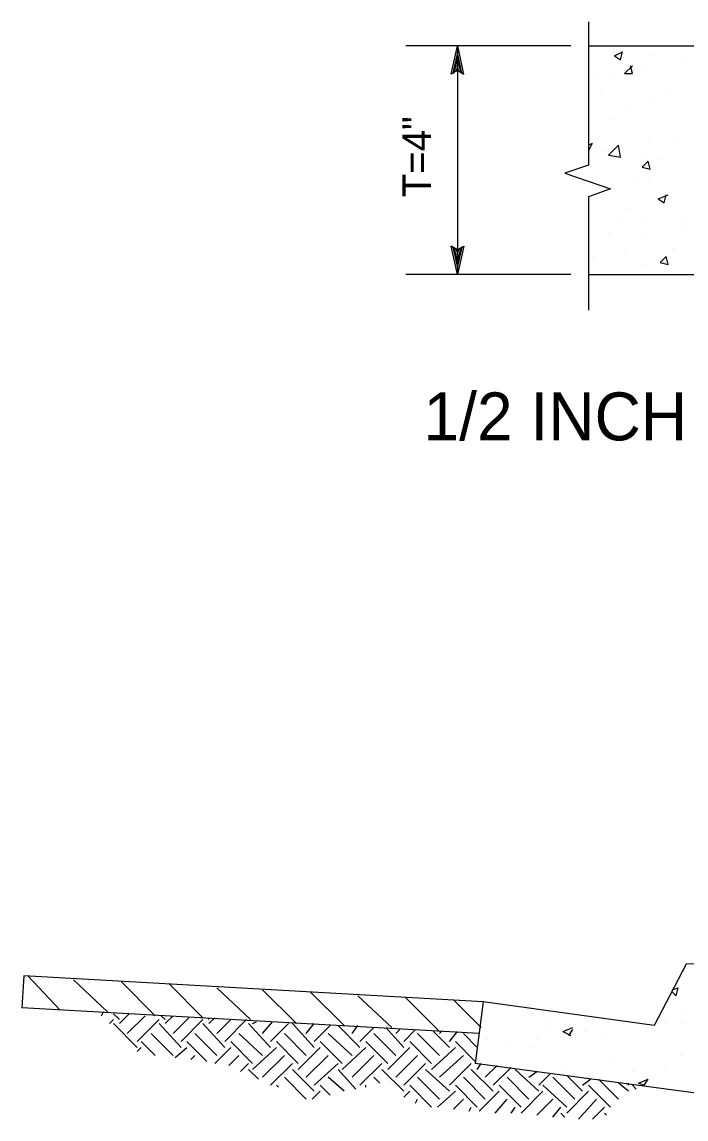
# Model space of a CAD drawing. Extents: x -118779 to -116979, y -104389 to -102939.
# Drawn here: x -118447.5 to -118309, y -103633.1 to -103404.1 of the extents above; entities that cross this region are included whole.
import ezdxf

# ---------------------------------------------------------------- set-up
doc = ezdxf.new("R2010")
doc.units = 0
for name, color, linetype in [('G-MARK', 7, 'Continuous'), ('G-TEXT', 7, 'Continuous'), ('Misc CnstDet(22)', 7, 'Continuous')]:
    doc.layers.add(name, color=color, linetype=linetype)

msp = doc.modelspace()

# ---------------------------------------------------------------- linework, layer by layer
at = {"layer": 'G-MARK'}
for p, q in [((-118333.05, -103409.09), (-118367.48, -103409.09)), ((-118356.7, -103409.09), (-118356.7, -103456.79)), ((-118333.05, -103456.79), (-118367.48, -103456.79))]:
    msp.add_line(p, q, dxfattribs=at)
at = {"layer": 'G-TEXT'}
for points in [[(-118358.01, -103415), (-118356.7, -103409.09), (-118355.39, -103415), (-118355.74, -103414.79), (-118356.69, -103410.46), (-118357.67, -103414.79), (-118357.32, -103414.58), (-118356.7, -103411.81), (-118356.08, -103414.58), (-118356.43, -103414.37), (-118356.7, -103413.17), (-118356.97, -103414.37), (-118356.7, -103414.21), (-118355.39, -103415), (-118356.7, -103414.21)], [(-118355.38, -103450.88), (-118356.7, -103456.79), (-118358.01, -103450.88), (-118357.66, -103451.09), (-118356.7, -103455.42), (-118355.73, -103451.09), (-118356.08, -103451.3), (-118356.69, -103454.07), (-118357.31, -103451.3), (-118356.96, -103451.51), (-118356.69, -103452.71), (-118356.42, -103451.51), (-118356.7, -103451.67), (-118358.01, -103450.88), (-118356.7, -103451.67)]]:
    msp.add_lwpolyline(points, close=True, dxfattribs=at)
at = {"layer": 'Misc CnstDet(22)'}
for p, q in [((-118329.32, -103409.09), (-118254.66, -103409.09)), ((-118329.32, -103409.09), (-118329.32, -103409.09)), ((-118323.93, -103411.16), (-118322.27, -103410.33)), ((-118323.93, -103411.16), (-118322.69, -103411.99)), ((-118322.69, -103411.99), (-118322.27, -103410.33)), ((-118316.05, -103411.16), (-118316.05, -103411.16)), ((-118321.86, -103414.9), (-118320.2, -103413.24)), ((-118320.2, -103414.9), (-118320.61, -103413.24)), ((-118317.29, -103414.07), (-118317.29, -103414.07)), ((-118309.41, -103412.41), (-118309.41, -103412.41)), ((-118327.25, -103415.31), (-118327.25, -103415.31)), ((-118324.76, -103415.31), (-118324.76, -103415.31)), ((-118321.86, -103414.9), (-118320.2, -103414.9)), ((-118326.83, -103418.22), (-118326.83, -103418.22)), ((-118316.46, -103419.87), (-118316.46, -103419.87)), ((-118312.73, -103419.04), (-118312.73, -103419.04)), ((-118321.03, -103421.95), (-118321.03, -103421.95)), ((-118324.34, -103424.44), (-118324.34, -103424.44)), ((-118329.32, -103431.07), (-118328.49, -103429.41)), ((-118329.32, -103429.83), (-118328.49, -103429.41)), ((-118325.17, -103431.9), (-118323.1, -103429.83)), ((-118322.69, -103432.32), (-118323.1, -103429.83)), ((-118316.88, -103428.58), (-118316.88, -103428.58)), ((-118310.66, -103428.17), (-118310.66, -103428.17)), ((-118329.32, -103431.07), (-118329.32, -103431.07)), ((-118326, -103431.07), (-118326, -103431.07)), ((-118325.17, -103431.9), (-118322.69, -103432.32)), ((-118317.71, -103432.32), (-118317.71, -103432.32)), ((-118330.98, -103434.81), (-118330.98, -103434.81)), ((-118318.12, -103434.39), (-118316.88, -103433.15)), ((-118318.12, -103434.39), (-118316.46, -103434.81)), ((-118316.46, -103434.81), (-118316.88, -103433.15)), ((-118314.39, -103432.73), (-118314.39, -103432.73)), ((-118319.78, -103436.88), (-118319.78, -103436.88)), ((-118316.88, -103437.29), (-118316.88, -103437.29)), ((-118314.8, -103441.03), (-118312.73, -103440.2)), ((-118314.8, -103441.03), (-118313.56, -103441.86)), ((-118313.56, -103441.86), (-118313.15, -103440.2)), ((-118321.44, -103443.1), (-118321.44, -103443.1)), ((-118314.8, -103442.27), (-118314.8, -103442.27)), ((-118323.1, -103445.59), (-118323.1, -103445.59)), ((-118317.29, -103446), (-118317.29, -103446)), ((-118309.83, -103446), (-118309.83, -103446)), ((-118325.17, -103448.49), (-118325.17, -103448.49)), ((-118309, -103446.42), (-118309, -103446.42)), ((-118317.29, -103449.32), (-118317.29, -103449.32)), ((-118321.86, -103452.64), (-118321.86, -103452.64)), ((-118314.39, -103454.3), (-118313.15, -103453.06)), ((-118312.73, -103454.71), (-118313.15, -103453.06)), ((-118311.9, -103451.4), (-118311.9, -103451.4)), ((-118328.49, -103453.47), (-118328.49, -103453.47)), ((-118317.71, -103454.71), (-118317.71, -103454.71)), ((-118314.39, -103454.3), (-118312.73, -103454.71)), ((-118356.7, -103456.79), (-118356.7, -103456.79)), ((-118329.32, -103456.79), (-118181.25, -103456.79)), ((-118329.32, -103456.79), (-118329.32, -103456.79)), ((-118100.79, -103593.66), (-118309, -103600.71)), ((-118309, -103600.71), (-118315.63, -103613.57)), ((-118309.83, -103601.96), (-118309.83, -103601.96)), ((-118447.11, -103603.2), (-118447.53, -103609.84)), ((-118351.3, -103608.59), (-118447.11, -103603.2)), ((-118439.65, -103610.25), (-118446.28, -103603.2)), ((-118429.69, -103610.67), (-118436.75, -103604.03)), ((-118419.74, -103611.5), (-118426.79, -103604.44)), ((-118409.79, -103611.91), (-118416.84, -103604.86)), ((-118399.83, -103612.32), (-118406.88, -103605.69)), ((-118390.29, -103613.15), (-118397.34, -103606.1)), ((-118380.34, -103613.57), (-118387.39, -103606.52)), ((-118311.9, -103606.1), (-118310.66, -103605.69)), ((-118311.9, -103606.52), (-118311.07, -103607.35)), ((-118311.07, -103607.35), (-118310.66, -103605.69)), ((-118370.38, -103613.98), (-118377.43, -103607.35)), ((-118360.43, -103614.81), (-118367.48, -103607.76)), ((-118351.72, -103613.98), (-118357.53, -103608.18)), ((-118351.3, -103608.59), (-118352.96, -103621.45)), ((-118315.63, -103613.57), (-118351.3, -103608.59)), ((-118350.89, -103608.59), (-118350.89, -103608.59)), ((-118352.13, -103615.23), (-118447.53, -103609.84)), ((-118430.94, -103611.5), (-118430.52, -103610.67)), ((-118427.21, -103612.32), (-118428.45, -103611.08)), ((-118427.21, -103613.15), (-118425.13, -103611.08)), ((-118309.83, -103611.08), (-118309.83, -103611.08)), ((-118429.28, -103613.15), (-118428.45, -103612.32)), ((-118423.47, -103618.13), (-118428.45, -103613.15)), ((-118425.55, -103615.23), (-118421.81, -103611.5)), ((-118423.47, -103616.89), (-118418.91, -103612.32)), ((-118414.35, -103618.13), (-118418.91, -103613.15)), ((-118417.67, -103612.32), (-118418.5, -103611.5)), ((-118417.67, -103613.15), (-118416.01, -103611.5)), ((-118416.01, -103615.23), (-118412.69, -103611.91)), ((-118414.35, -103616.89), (-118409.79, -103612.32)), ((-118405.22, -103618.13), (-118409.79, -103613.15)), ((-118408.54, -103612.32), (-118408.54, -103611.91)), ((-118408.54, -103613.15), (-118407.3, -103611.91)), ((-118406.88, -103615.23), (-118403.98, -103612.32)), ((-118405.22, -103616.89), (-118400.66, -103612.32)), ((-118395.68, -103618.13), (-118400.25, -103613.15)), ((-118399.42, -103613.15), (-118398.59, -103612.74)), ((-118397.34, -103615.23), (-118395.27, -103612.74)), ((-118395.68, -103616.89), (-118391.95, -103613.15)), ((-118386.56, -103618.13), (-118391.12, -103613.15)), ((-118389.88, -103613.15), (-118389.88, -103613.15)), ((-118388.22, -103615.23), (-118386.56, -103613.15)), ((-118351.72, -103611.5), (-118351.72, -103611.5)), ((-118337.62, -103611.91), (-118337.62, -103611.91)), ((-118323.51, -103612.74), (-118323.51, -103612.74)), ((-118323.51, -103612.74), (-118323.51, -103612.74)), ((-118313.56, -103612.74), (-118313.56, -103612.74)), ((-118310.24, -103612.74), (-118310.24, -103612.74)), ((-118309.41, -103613.15), (-118309.41, -103613.15)), ((-118416.01, -103619.79), (-118420.57, -103615.23)), ((-118406.88, -103619.79), (-118411.44, -103615.23)), ((-118397.34, -103619.79), (-118402.32, -103615.23)), ((-118388.22, -103619.79), (-118392.78, -103615.23)), ((-118386.56, -103616.89), (-118383.24, -103613.57)), ((-118378.68, -103619.79), (-118383.66, -103615.23)), ((-118377.02, -103618.13), (-118381.58, -103613.57)), ((-118378.68, -103615.23), (-118377.43, -103613.57)), ((-118377.02, -103616.89), (-118374.12, -103613.98)), ((-118369.55, -103619.79), (-118374.12, -103615.23)), ((-118367.89, -103618.13), (-118371.63, -103613.98)), ((-118369.55, -103615.23), (-118368.72, -103614.4)), ((-118367.89, -103616.89), (-118365.41, -103614.4)), ((-118360.43, -103619.79), (-118364.99, -103615.23)), ((-118358.36, -103618.13), (-118361.67, -103614.81)), ((-118360.43, -103615.23), (-118360.01, -103614.81)), ((-118358.36, -103616.89), (-118356.7, -103614.81)), ((-118352.55, -103618.13), (-118355.45, -103615.23)), ((-118337.2, -103614.81), (-118337.2, -103614.81)), ((-118334.71, -103614.81), (-118332.64, -103613.98)), ((-118334.71, -103614.81), (-118333.05, -103615.64)), ((-118333.47, -103615.64), (-118332.64, -103614.4)), ((-118330.15, -103614.81), (-118330.15, -103614.81)), ((-118325.59, -103615.23), (-118325.59, -103615.23)), ((-118419.74, -103619.79), (-118422.64, -103616.89)), ((-118408.96, -103621.03), (-118413.1, -103616.89)), ((-118399.42, -103621.45), (-118403.98, -103616.89)), ((-118389.88, -103621.45), (-118394.44, -103616.89)), ((-118380.75, -103621.45), (-118385.31, -103616.89)), ((-118371.21, -103621.45), (-118375.78, -103616.89)), ((-118362.09, -103621.45), (-118366.65, -103616.89)), ((-118352.96, -103621.03), (-118357.11, -103616.89)), ((-118350.47, -103616.47), (-118350.47, -103616.47)), ((-118346.74, -103616.89), (-118346.74, -103616.89)), ((-118340.11, -103616.06), (-118340.11, -103616.06)), ((-118423.47, -103618.96), (-118422.64, -103618.13)), ((-118415.59, -103620.21), (-118413.1, -103618.13)), ((-118412.27, -103620.62), (-118411.44, -103619.79)), ((-118407.3, -103621.45), (-118403.98, -103618.13)), ((-118404.39, -103621.86), (-118402.32, -103619.79)), ((-118399.42, -103622.69), (-118394.44, -103618.13)), ((-118397.34, -103624.35), (-118392.78, -103619.79)), ((-118389.88, -103622.69), (-118385.31, -103618.13)), ((-118388.22, -103624.35), (-118383.66, -103619.79)), ((-118380.75, -103622.69), (-118375.78, -103618.13)), ((-118378.68, -103624.35), (-118374.12, -103619.79)), ((-118371.21, -103622.69), (-118366.65, -103618.13)), ((-118369.55, -103624.35), (-118364.99, -103619.79)), ((-118362.09, -103622.69), (-118357.11, -103618.13)), ((-118360.43, -103624.35), (-118355.45, -103619.79)), ((-118340.93, -103618.13), (-118340.93, -103618.13)), ((-118310.24, -103619.79), (-118310.24, -103619.79)), ((-118401.91, -103623.11), (-118400.25, -103621.45)), ((-118395.68, -103626.01), (-118391.12, -103621.45)), ((-118386.56, -103626.01), (-118381.58, -103621.45)), ((-118377.02, -103626.01), (-118372.46, -103621.45)), ((-118367.89, -103626.01), (-118363.33, -103621.45)), ((-118358.36, -103626.01), (-118353.79, -103621.45)), ((-118297.8, -103628.92), (-118352.96, -103621.45)), ((-118352.55, -103621.45), (-118352.55, -103621.45)), ((-118352.55, -103622.69), (-118351.72, -103621.45)), ((-118350.89, -103624.35), (-118348.4, -103621.86)), ((-118349.23, -103626.01), (-118345.5, -103622.28)), ((-118348.4, -103621.86), (-118348.4, -103621.86)), ((-118323.93, -103621.45), (-118323.93, -103621.45)), ((-118313.56, -103622.28), (-118313.56, -103622.28)), ((-118398.17, -103624.77), (-118400.25, -103622.69)), ((-118388.22, -103628.92), (-118392.78, -103624.35)), ((-118386.56, -103627.26), (-118391.12, -103622.69)), ((-118380.34, -103627.26), (-118383.66, -103624.35)), ((-118377.85, -103626.84), (-118381.58, -103622.69)), ((-118372.87, -103625.6), (-118374.12, -103624.35)), ((-118367.89, -103627.26), (-118372.46, -103622.69)), ((-118360.43, -103628.92), (-118364.99, -103624.35)), ((-118358.36, -103627.26), (-118363.33, -103622.69)), ((-118350.89, -103628.92), (-118355.45, -103624.35)), ((-118349.23, -103627.26), (-118353.79, -103622.69)), ((-118341.76, -103628.92), (-118346.33, -103624.35)), ((-118339.69, -103627.26), (-118344.67, -103622.69)), ((-118341.76, -103624.35), (-118340.11, -103623.11)), ((-118339.69, -103626.01), (-118337.2, -103623.52)), ((-118332.22, -103628.92), (-118336.79, -103624.35)), ((-118334.3, -103622.69), (-118334.3, -103622.69)), ((-118330.57, -103627.26), (-118333.88, -103623.94)), ((-118332.22, -103624.35), (-118332.22, -103624.35)), ((-118330.57, -103626.01), (-118328.91, -103624.77)), ((-118323.1, -103628.92), (-118327.25, -103624.77)), ((-118320.2, -103623.11), (-118320.2, -103623.11)), ((-118320.2, -103623.11), (-118320.2, -103623.11)), ((-118318.95, -103625.6), (-118316.88, -103624.77)), ((-118317.71, -103626.01), (-118316.88, -103624.77)), ((-118394.02, -103626.43), (-118394.44, -103626.01)), ((-118383.24, -103628.09), (-118385.31, -103626.01)), ((-118375.78, -103626.43), (-118375.78, -103626.01)), ((-118362.09, -103630.57), (-118366.65, -103626.01)), ((-118352.55, -103630.57), (-118357.11, -103626.01)), ((-118343.42, -103630.57), (-118347.99, -103626.01)), ((-118333.88, -103630.57), (-118338.86, -103626.01)), ((-118324.76, -103630.57), (-118329.32, -103626.01)), ((-118321.03, -103627.26), (-118323.1, -103625.6)), ((-118321.03, -103626.01), (-118321.03, -103625.6)), ((-118319.37, -103626.84), (-118320.2, -103626.01)), ((-118318.95, -103625.6), (-118317.71, -103626.01)), ((-118386.97, -103628.92), (-118385.31, -103627.26)), ((-118367.89, -103628.5), (-118366.65, -103627.26)), ((-118365.41, -103629.74), (-118364.99, -103628.92)), ((-118360.84, -103630.57), (-118357.11, -103627.26)), ((-118357.53, -103630.99), (-118355.45, -103628.92)), ((-118352.13, -103631.4), (-118347.99, -103627.26)), ((-118348.82, -103631.82), (-118346.33, -103628.92)), ((-118343.42, -103631.82), (-118338.86, -103627.26)), ((-118340.11, -103632.23), (-118336.79, -103628.92)), ((-118333.88, -103631.82), (-118329.32, -103627.26)), ((-118331.4, -103633.06), (-118327.66, -103628.92)), ((-118354.21, -103631.4), (-118353.79, -103630.57)), ((-118345.5, -103631.82), (-118344.67, -103630.57)), ((-118336.79, -103632.65), (-118335.13, -103630.57)), ((-118328.49, -103633.06), (-118326, -103630.57)), ((-118344.67, -103631.82), (-118344.67, -103631.82)), ((-118334.3, -103632.65), (-118335.13, -103631.82)), ((-118325.59, -103632.23), (-118326, -103631.82))]:
    msp.add_line(p, q, dxfattribs=at)
msp.add_lwpolyline([(-118329.32, -103404.11), (-118329.32, -103433.98), (-118334.3, -103435.64), (-118324.76, -103438.95), (-118329.32, -103440.61), (-118329.32, -103464.25)], dxfattribs=at)

# ---------------------------------------------------------------- texts
msp.add_text('T=4"', height=6, rotation=90, dxfattribs=at).set_placement((-118362.18, -103440.7))
msp.add_text('1/2 INCH EXPANSION JOINT (EJ)', height=10, dxfattribs=at).set_placement((-118363.76, -103491.43))

doc.saveas('drawing.dxf')
